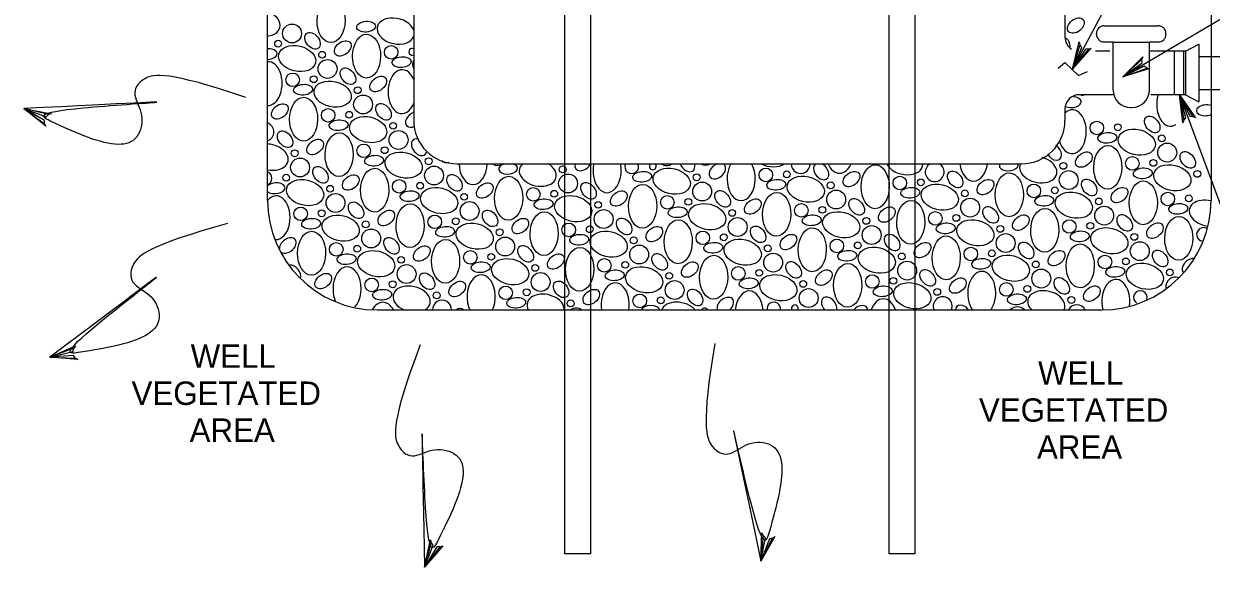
# Model space of a CAD drawing. Extents: x 636462 to 637367, y 299944 to 300538.
# Drawn here: x 636731.3 to 636883.5, y 300235.2 to 300304.9 of the extents above; entities that cross this region are included whole.
import ezdxf

# ---------------------------------------------------------------- set-up
doc = ezdxf.new("R2010")
doc.units = 0
doc.layers.add('1', color=7, linetype='Continuous')
doc.layers.add('Default', color=7, linetype='Continuous')

msp = doc.modelspace()

# ---------------------------------------------------------------- linework, layer by layer
at = {"layer": '1'}
msp.add_lwpolyline([(636863.84, 300299.17), (636864.72, 300299.91), (636866.46, 300298.24), (636867.63, 300298.74)], dxfattribs=at)
at = {"layer": 'Default'}
for p, q in [((636865.7, 300299.03), (636894.03, 300352.14)), ((636952.82, 300345.46), (636872.15, 300298.08)), ((636781.25, 300337), (636781.25, 300292.48)), ((636864.72, 300337), (636864.72, 300303.18)), ((636869.74, 300304.6), (636876.7, 300304.6)), ((636868.77, 300303.5), (636868.77, 300303.63)), ((636877.67, 300303.5), (636877.67, 300303.63)), ((636870.48, 300301.33), (636868.65, 300301.33)), ((636870.89, 300302.52), (636869.74, 300302.52)), ((636870.89, 300296.37), (636870.89, 300302.52)), ((636870.89, 300302.52), (636875.55, 300302.52)), ((636875.55, 300296.37), (636875.55, 300302.52)), ((636876.7, 300302.52), (636875.55, 300302.52)), ((636880.19, 300301.33), (636875.58, 300301.33)), ((636878.72, 300301.33), (636878.72, 300295.76)), ((636879.91, 300301.33), (636879.91, 300295.76)), ((636880.19, 300301.33), (636881.89, 300302.24)), ((636880.19, 300301.33), (636880.19, 300295.76)), ((636881.89, 300302.24), (636881.89, 300294.85)), ((636881.89, 300300.65), (636917.52, 300300.65)), ((636870.9, 300295.76), (636866.58, 300295.76)), ((636880.19, 300295.76), (636875.72, 300295.76)), ((636879.41, 300295.76), (636894.23, 300255.85)), ((636880.19, 300295.76), (636881.89, 300294.85)), ((636881.89, 300296.45), (636917.52, 300296.45)), ((636864.72, 300293.91), (636864.72, 300292.48)), ((636873.14, 300294.12), (636873.3, 300294.12)), ((636786.81, 300286.91), (636859.16, 300286.91)), ((636800.61, 300286.91), (636803.89, 300286.91)), ((636842.21, 300286.91), (636845.49, 300286.91))]:
    msp.add_line(p, q, dxfattribs=at)
for points in [[(636762.51, 300282.23), (636762.51, 300347.25)], [(636883.46, 300347.25), (636883.46, 300282.23)], [(636800.61, 300286.91), (636800.61, 300342.56)], [(636803.89, 300342.56), (636803.89, 300286.91)], [(636842.21, 300286.91), (636842.21, 300342.56)], [(636845.49, 300342.56), (636845.49, 300286.91)], [(636867.77, 300301.59), (636868.1, 300301.72), (636865.7, 300299.03), (636867.77, 300301.59), (636867.35, 300301.59), (636865.7, 300299.03), (636866.89, 300301.83), (636866.64, 300302.17), (636865.7, 300299.03), (636866.55, 300302.53), (636866.64, 300302.17)], [(636875.26, 300299.19), (636875.6, 300299.14), (636872.15, 300298.08), (636875.26, 300299.19), (636874.9, 300299.41), (636872.15, 300298.08), (636874.62, 300299.86), (636874.59, 300300.28), (636872.15, 300298.08), (636874.7, 300300.64), (636874.59, 300300.28)], [(636879.95, 300292.51), (636879.83, 300292.18), (636879.41, 300295.76), (636879.95, 300292.51), (636880.23, 300292.82), (636879.41, 300295.76), (636880.72, 300293.01), (636881.13, 300292.97), (636879.41, 300295.76), (636881.47, 300292.8), (636881.13, 300292.97)], [(636733.92, 300292.05), (636734.07, 300291.73), (636731.25, 300293.98), (636733.92, 300292.05), (636733.9, 300292.47), (636731.25, 300293.98), (636734.11, 300292.94), (636734.43, 300293.21), (636731.25, 300293.98), (636734.8, 300293.32), (636734.43, 300293.21)], [(636803.89, 300286.91), (636803.89, 300236.94), (636800.61, 300236.94), (636800.61, 300286.91)], [(636845.49, 300286.91), (636845.49, 300236.94), (636842.21, 300236.94), (636842.21, 300286.91)], [(636869.41, 300268.17), (636776.56, 300268.17)], [(636737.88, 300262.01), (636738.18, 300261.84), (636734.59, 300262.12), (636737.88, 300262.01), (636737.63, 300262.35), (636734.59, 300262.12), (636737.54, 300262.87), (636737.66, 300263.27), (636734.59, 300262.12), (636737.89, 300263.56), (636737.66, 300263.27)], [(636784.64, 300237.81), (636784.96, 300237.95), (636782.63, 300235.2), (636784.64, 300237.81), (636784.22, 300237.8), (636782.63, 300235.2), (636783.75, 300238.03), (636783.5, 300238.36), (636782.63, 300235.2), (636783.4, 300238.72), (636783.5, 300238.36)], [(636827.25, 300238.92), (636827.54, 300239.12), (636825.76, 300235.98), (636827.25, 300238.92), (636826.84, 300238.83), (636825.76, 300235.98), (636826.33, 300238.97), (636826.02, 300239.25), (636825.76, 300235.98), (636825.85, 300239.59), (636826.02, 300239.25)]]:
    msp.add_lwpolyline(points, dxfattribs=at)
for centre, radius in [((636765.64, 300303.62), 1.21), ((636763.86, 300302.31), 0.435), ((636769.5, 300300.89), 0.435), ((636778.35, 300301.21), 0.869), ((636770.2, 300299.07), 1.21), ((636765.73, 300297.68), 0.869), ((636768.42, 300297.75), 0.435), ((636774.05, 300296.34), 0.435), ((636774.75, 300294.52), 1.21), ((636770.28, 300293.13), 0.869), ((636772.97, 300293.2), 0.435), ((636778.6, 300291.78), 0.435), ((636868.82, 300291.51), 0.869), ((636871.51, 300291.59), 0.435), ((636779.3, 300289.97), 1.21), ((636877.14, 300290.17), 0.435), ((636774.83, 300288.58), 0.869), ((636777.52, 300288.65), 0.435), ((636877.84, 300288.35), 1.21), ((636766.67, 300286.44), 1.21), ((636765.98, 300288.26), 0.435), ((636783.16, 300287.23), 0.435), ((636873.37, 300286.96), 0.869), ((636876.06, 300287.03), 0.435), ((636783.85, 300285.41), 1.21), ((636800.34, 300286.2), 0.435), ((636826.38, 300285.49), 0.869), ((636829.07, 300285.56), 0.435), ((636865.21, 300284.83), 1.21), ((636864.52, 300286.64), 0.435), ((636881.7, 300285.62), 0.435), ((636764.89, 300285.13), 0.435), ((636779.38, 300284.02), 0.869), ((636782.07, 300284.1), 0.435), ((636801.03, 300284.39), 1.21), ((636818.22, 300283.36), 1.21), ((636817.52, 300285.18), 0.435), ((636834.7, 300284.15), 0.435), ((636843.56, 300284.46), 0.869), ((636846.25, 300284.54), 0.435), ((636860.74, 300283.44), 0.869), ((636771.22, 300281.89), 1.21), ((636770.53, 300283.71), 0.435), ((636787.71, 300282.68), 0.435), ((636796.57, 300283), 0.869), ((636799.26, 300283.07), 0.435), ((636813.75, 300281.97), 0.869), ((636835.4, 300282.33), 1.21), ((636851.89, 300283.12), 0.435), ((636863.43, 300283.51), 0.435), ((636877.92, 300282.41), 0.869), ((636880.61, 300282.48), 0.435), ((636766.75, 300280.5), 0.869), ((636788.41, 300280.86), 1.21), ((636804.89, 300281.65), 0.435), ((636816.44, 300282.04), 0.435), ((636830.93, 300280.94), 0.869), ((636833.62, 300281.01), 0.435), ((636852.58, 300281.3), 1.21), ((636869.76, 300280.27), 1.21), ((636869.07, 300282.09), 0.435), ((636769.44, 300280.57), 0.435), ((636783.94, 300279.47), 0.869), ((636786.63, 300279.54), 0.435), ((636805.59, 300279.83), 1.21), ((636822.77, 300278.81), 1.21), ((636822.07, 300280.62), 0.435), ((636839.26, 300279.59), 0.435), ((636848.11, 300279.91), 0.869), ((636850.8, 300279.98), 0.435), ((636865.29, 300278.88), 0.869), ((636775.78, 300277.34), 1.21), ((636775.08, 300279.15), 0.435), ((636792.26, 300278.13), 0.435), ((636801.12, 300278.44), 0.869), ((636803.81, 300278.52), 0.435), ((636818.3, 300277.42), 0.869), ((636839.95, 300277.78), 1.21), ((636856.44, 300278.57), 0.435), ((636867.98, 300278.96), 0.435), ((636771.31, 300275.95), 0.869), ((636792.96, 300276.31), 1.21), ((636809.44, 300277.1), 0.435), ((636820.99, 300277.49), 0.435), ((636835.48, 300276.39), 0.869), ((636838.17, 300276.46), 0.435), ((636857.13, 300276.75), 1.21), ((636874.32, 300275.72), 1.21), ((636873.62, 300277.54), 0.435), ((636774, 300276.02), 0.435), ((636788.49, 300274.92), 0.869), ((636791.18, 300274.99), 0.435), ((636810.14, 300275.28), 1.21), ((636827.32, 300274.25), 1.21), ((636826.63, 300276.07), 0.435), ((636843.81, 300275.04), 0.435), ((636852.66, 300275.36), 0.869), ((636855.36, 300275.43), 0.435), ((636869.85, 300274.33), 0.869), ((636780.33, 300272.78), 1.21), ((636779.63, 300274.6), 0.435), ((636796.82, 300273.57), 0.435), ((636805.67, 300273.89), 0.869), ((636808.36, 300273.96), 0.435), ((636822.85, 300272.86), 0.869), ((636844.5, 300273.22), 1.21), ((636860.99, 300274.01), 0.435), ((636872.54, 300274.4), 0.435), ((636775.86, 300271.39), 0.869), ((636797.51, 300271.76), 1.21), ((636814, 300272.55), 0.435), ((636825.54, 300272.94), 0.435), ((636840.03, 300271.83), 0.869), ((636842.73, 300271.91), 0.435), ((636861.69, 300272.2), 1.21), ((636878.17, 300272.99), 0.435), ((636778.55, 300271.47), 0.435), ((636793.04, 300270.37), 0.869), ((636795.73, 300270.44), 0.435), ((636814.69, 300270.73), 1.21), ((636831.87, 300269.7), 1.21), ((636831.18, 300271.52), 0.435), ((636848.36, 300270.49), 0.435), ((636857.22, 300270.81), 0.869), ((636859.91, 300270.88), 0.435), ((636784.19, 300270.05), 0.435), ((636801.37, 300269.02), 0.435), ((636810.22, 300269.34), 0.869), ((636812.91, 300269.41), 0.435), ((636865.54, 300269.46), 0.435)]:
    msp.add_circle(centre, radius, dxfattribs=at)
for centre, radius, start, end in [((636869.74, 300303.63), 0.974, 90, 180), ((636876.7, 300303.63), 0.974, 360, 90), ((636866.58, 300303.18), 1.86, 180, 237.7912), ((636864.18, 300302.01), 1.21, 352.7201, 61.4233), ((636869.74, 300303.5), 0.974, 180, 270), ((636876.7, 300303.5), 0.974, 270, 0), ((636781.05, 300301.28), 0.435, 62.7415, 297.2585), ((636866.58, 300293.91), 1.86, 90, 180), ((636866.96, 300296.14), 0.435, 240.305, 299.695), ((636873.14, 300296.37), 2.25, 180, 270), ((636873.3, 300296.37), 2.25, 270, 0), ((636762.12, 300290.99), 1.21, 288.7446, 71.2554), ((636786.81, 300292.48), 5.57, 180, 270), ((636859.16, 300292.48), 5.57, 270, 360), ((636762.2, 300285.05), 0.869, 290.6346, 69.3654), ((636792.01, 300287.55), 0.869, 227.2713, 312.7287), ((636809.19, 300286.52), 0.869, 153.3644, 26.6356), ((636811.89, 300286.59), 0.435, 133.1772, 46.8228), ((636813.66, 300287.91), 1.21, 235.6642, 304.3358), ((636830.85, 300286.88), 1.21, 178.6807, 1.3193), ((636848.03, 300285.85), 1.21, 119.3321, 60.6679), ((636776.56, 300282.23), 14.05, 180, 270), ((636869.41, 300282.23), 14.05, 270, 0), ((636882.48, 300277.86), 0.869, 58.5112, 260.9176), ((636878.87, 300271.17), 1.21, 68.7134, 188.0124), ((636874.4, 300269.78), 0.869, 344.543, 239.3176), ((636784.88, 300268.23), 1.21, 357.1734, 182.8266), ((636827.4, 300268.31), 0.869, 350.8755, 189.1245), ((636849.06, 300268.67), 1.21, 335.6413, 204.3587), ((636802.06, 300267.2), 1.21, 53.0783, 126.9217), ((636818.55, 300267.99), 0.435, 24.3232, 155.6768), ((636830.1, 300268.38), 0.435, 331.017, 208.983), ((636866.24, 300267.64), 1.21, 25.8695, 154.1305)]:
    msp.add_arc(centre, radius, start, end, dxfattribs=at)
for centre, major_axis, ratio in [((636770.65, 300305.26), (0.03, 2.81), 0.641702), ((636866.13, 300304.63), (0.938, 0.766), 0.672414), ((636775.14, 300304.49), (1.21, 0.09), 0.56568), ((636768.27, 300302.68), (-0.766, 0.938), 0.672414), ((636772.14, 300301.7), (0.938, 0.766), 0.672414), ((636775.2, 300300.71), (0.03, 2.81), 0.641702), ((636766.3, 300300.4), (-2.36, 0.55), 0.672414), ((636779.69, 300299.94), (1.21, 0.09), 0.56568), ((636772.82, 300298.13), (-0.766, 0.938), 0.672414), ((636776.7, 300297.14), (0.938, 0.766), 0.672414), ((636767.06, 300296.41), (1.21, 0.09), 0.56568), ((636770.85, 300295.84), (-2.36, 0.55), 0.672414), ((636767.12, 300292.63), (0.03, 2.81), 0.641702), ((636764.07, 300293.62), (0.938, 0.766), 0.672414), ((636777.38, 300293.58), (-0.766, 0.938), 0.672414), ((636771.62, 300291.86), (1.21, 0.09), 0.56568), ((636775.4, 300291.29), (-2.36, 0.55), 0.672414), ((636875.92, 300291.96), (-0.766, 0.938), 0.672414), ((636764.75, 300290.06), (-0.766, 0.938), 0.672414), ((636771.68, 300288.08), (0.03, 2.81), 0.641702), ((636870.16, 300290.24), (1.21, 0.09), 0.56568), ((636873.94, 300289.68), (-2.36, 0.55), 0.672414), ((636768.62, 300289.07), (0.938, 0.766), 0.672414), ((636870.22, 300286.46), (0.03, 2.81), 0.641702), ((636776.17, 300287.31), (1.21, 0.09), 0.56568), ((636779.95, 300286.74), (-2.36, 0.55), 0.672414), ((636867.16, 300287.45), (0.938, 0.766), 0.672414), ((636880.47, 300287.41), (-0.766, 0.938), 0.672414), ((636769.3, 300285.5), (-0.766, 0.938), 0.672414), ((636776.23, 300283.53), (0.03, 2.81), 0.641702), ((636810.53, 300285.25), (1.21, 0.09), 0.56568), ((636814.32, 300284.68), (-2.36, 0.55), 0.672414), ((636837.35, 300284.95), (0.938, 0.766), 0.672414), ((636840.4, 300283.97), (0.03, 2.81), 0.641702), ((636850.66, 300284.91), (-0.766, 0.938), 0.672414), ((636874.71, 300285.69), (1.21, 0.09), 0.56568), ((636878.49, 300285.12), (-2.36, 0.55), 0.672414), ((636767.32, 300283.22), (-2.36, 0.55), 0.672414), ((636773.17, 300284.51), (0.938, 0.766), 0.672414), ((636786.48, 300284.47), (-0.766, 0.938), 0.672414), ((636790.36, 300283.48), (0.938, 0.766), 0.672414), ((636793.41, 300282.5), (0.03, 2.81), 0.641702), ((636803.66, 300283.45), (-0.766, 0.938), 0.672414), ((636810.59, 300281.47), (0.03, 2.81), 0.641702), ((636827.72, 300284.22), (1.21, 0.09), 0.56568), ((636831.5, 300283.66), (-2.36, 0.55), 0.672414), ((636848.68, 300282.63), (-2.36, 0.55), 0.672414), ((636854.53, 300283.92), (0.938, 0.766), 0.672414), ((636857.59, 300282.94), (0.03, 2.81), 0.641702), ((636867.84, 300283.89), (-0.766, 0.938), 0.672414), ((636874.77, 300281.91), (0.03, 2.81), 0.641702), ((636780.72, 300282.76), (1.21, 0.09), 0.56568), ((636784.51, 300282.19), (-2.36, 0.55), 0.672414), ((636801.69, 300281.16), (-2.36, 0.55), 0.672414), ((636807.54, 300282.46), (0.938, 0.766), 0.672414), ((636820.85, 300282.42), (-0.766, 0.938), 0.672414), ((636827.77, 300280.44), (0.03, 2.81), 0.641702), ((636844.9, 300283.2), (1.21, 0.09), 0.56568), ((636862.08, 300282.17), (1.21, 0.09), 0.56568), ((636865.86, 300281.6), (-2.36, 0.55), 0.672414), ((636871.71, 300282.9), (0.938, 0.766), 0.672414), ((636773.85, 300280.95), (-0.766, 0.938), 0.672414), ((636780.78, 300278.98), (0.03, 2.81), 0.641702), ((636797.9, 300281.73), (1.21, 0.09), 0.56568), ((636815.09, 300280.7), (1.21, 0.09), 0.56568), ((636818.87, 300280.13), (-2.36, 0.55), 0.672414), ((636824.72, 300281.43), (0.938, 0.766), 0.672414), ((636838.03, 300281.39), (-0.766, 0.938), 0.672414), ((636841.9, 300280.4), (0.938, 0.766), 0.672414), ((636844.96, 300279.41), (0.03, 2.81), 0.641702), ((636855.21, 300280.36), (-0.766, 0.938), 0.672414), ((636879.26, 300281.14), (1.21, 0.09), 0.56568), ((636768.09, 300279.23), (1.21, 0.09), 0.56568), ((636771.88, 300278.66), (-2.36, 0.55), 0.672414), ((636777.73, 300279.96), (0.938, 0.766), 0.672414), ((636791.03, 300279.92), (-0.766, 0.938), 0.672414), ((636794.91, 300278.93), (0.938, 0.766), 0.672414), ((636797.96, 300277.95), (0.03, 2.81), 0.641702), ((636808.22, 300278.89), (-0.766, 0.938), 0.672414), ((636815.15, 300276.92), (0.03, 2.81), 0.641702), ((636832.27, 300279.67), (1.21, 0.09), 0.56568), ((636836.05, 300279.1), (-2.36, 0.55), 0.672414), ((636853.24, 300278.07), (-2.36, 0.55), 0.672414), ((636859.08, 300279.37), (0.938, 0.766), 0.672414), ((636862.14, 300278.39), (0.03, 2.81), 0.641702), ((636872.39, 300279.33), (-0.766, 0.938), 0.672414), ((636879.32, 300277.36), (0.03, 2.81), 0.641702), ((636768.15, 300275.45), (0.03, 2.81), 0.641702), ((636785.27, 300278.2), (1.21, 0.09), 0.56568), ((636789.06, 300277.63), (-2.36, 0.55), 0.672414), ((636806.24, 300276.61), (-2.36, 0.55), 0.672414), ((636812.09, 300277.9), (0.938, 0.766), 0.672414), ((636825.4, 300277.87), (-0.766, 0.938), 0.672414), ((636832.33, 300275.89), (0.03, 2.81), 0.641702), ((636849.45, 300278.64), (1.21, 0.09), 0.56568), ((636866.63, 300277.61), (1.21, 0.09), 0.56568), ((636870.42, 300277.05), (-2.36, 0.55), 0.672414), ((636876.27, 300278.34), (0.938, 0.766), 0.672414), ((636778.4, 300276.4), (-0.766, 0.938), 0.672414), ((636785.33, 300274.42), (0.03, 2.81), 0.641702), ((636802.46, 300277.18), (1.21, 0.09), 0.56568), ((636819.64, 300276.15), (1.21, 0.09), 0.56568), ((636823.42, 300275.58), (-2.36, 0.55), 0.672414), ((636829.27, 300276.88), (0.938, 0.766), 0.672414), ((636842.58, 300276.84), (-0.766, 0.938), 0.672414), ((636846.45, 300275.85), (0.938, 0.766), 0.672414), ((636849.51, 300274.86), (0.03, 2.81), 0.641702), ((636859.76, 300275.81), (-0.766, 0.938), 0.672414), ((636772.64, 300274.68), (1.21, 0.09), 0.56568), ((636776.43, 300274.11), (-2.36, 0.55), 0.672414), ((636782.28, 300275.41), (0.938, 0.766), 0.672414), ((636795.59, 300275.37), (-0.766, 0.938), 0.672414), ((636799.46, 300274.38), (0.938, 0.766), 0.672414), ((636802.52, 300273.39), (0.03, 2.81), 0.641702), ((636812.77, 300274.34), (-0.766, 0.938), 0.672414), ((636819.7, 300272.37), (0.03, 2.81), 0.641702), ((636836.82, 300275.12), (1.21, 0.09), 0.56568), ((636840.61, 300274.55), (-2.36, 0.55), 0.672414), ((636857.79, 300273.52), (-2.36, 0.55), 0.672414), ((636863.64, 300274.82), (0.938, 0.766), 0.672414), ((636866.69, 300273.83), (0.03, 2.81), 0.641702), ((636876.94, 300274.78), (-0.766, 0.938), 0.672414), ((636789.83, 300273.65), (1.21, 0.09), 0.56568), ((636793.61, 300273.08), (-2.36, 0.55), 0.672414), ((636810.79, 300272.05), (-2.36, 0.55), 0.672414), ((636816.64, 300273.35), (0.938, 0.766), 0.672414), ((636829.95, 300273.31), (-0.766, 0.938), 0.672414), ((636836.88, 300271.34), (0.03, 2.81), 0.641702), ((636854, 300274.09), (1.21, 0.09), 0.56568), ((636871.18, 300273.06), (1.21, 0.09), 0.56568), ((636874.97, 300272.49), (-2.36, 0.55), 0.672414), ((636769.65, 300271.88), (0.938, 0.766), 0.672414), ((636782.96, 300271.85), (-0.766, 0.938), 0.672414), ((636807.01, 300272.62), (1.21, 0.09), 0.56568), ((636824.19, 300271.59), (1.21, 0.09), 0.56568), ((636827.98, 300271.03), (-2.36, 0.55), 0.672414), ((636833.82, 300272.32), (0.938, 0.766), 0.672414), ((636847.13, 300272.29), (-0.766, 0.938), 0.672414), ((636851.01, 300271.3), (0.938, 0.766), 0.672414), ((636864.32, 300271.26), (-0.766, 0.938), 0.672414), ((636777.2, 300270.13), (1.21, 0.09), 0.56568), ((636786.83, 300270.86), (0.938, 0.766), 0.672414), ((636800.14, 300270.82), (-0.766, 0.938), 0.672414), ((636804.01, 300269.83), (0.938, 0.766), 0.672414), ((636817.32, 300269.79), (-0.766, 0.938), 0.672414), ((636841.37, 300270.57), (1.21, 0.09), 0.56568), ((636845.16, 300270), (-2.36, 0.55), 0.672414), ((636868.19, 300270.27), (0.938, 0.766), 0.672414), ((636794.38, 300269.1), (1.21, 0.09), 0.56568), ((636858.56, 300269.54), (1.21, 0.09), 0.56568)]:
    msp.add_ellipse(centre, major_axis=major_axis, ratio=ratio, dxfattribs=at)
for centre, major_axis, ratio, start_param, end_param in [((636761.74, 300304.95), (-2.36, 0.55), 0.672414, 2.052765, 4.543621), ((636778.93, 300303.92), (-2.36, 0.55), 0.672414, 3.538888, 9.340684), ((636762.51, 300300.97), (1.21, 0.09), 0.56568, 4.667524, 7.816111), ((636762.57, 300297.19), (0.03, 2.81), 0.641702, 3.122831, 6.334752), ((636783.48, 300299.37), (-2.36, 0.55), 0.672414, 6.078453, 6.801119), ((636779.75, 300296.16), (0.03, 2.81), 0.641702, 5.322796, 10.417972), ((636865.6, 300294.8), (1.21, 0.09), 0.56568, 3.917971, 7.627832), ((636878.29, 300294.54), (0.03, 2.81), 0.641702, 1.127817, 3.535515), ((636781.25, 300292.59), (0.938, 0.766), 0.672414, 1.073393, 4.331942), ((636865.66, 300291.02), (0.03, 2.81), 0.641702, 1.987509, 6.849708), ((636882.79, 300293.77), (1.21, 0.09), 0.56568, 0.94046, 5.25999), ((636762.77, 300287.77), (-2.36, 0.55), 0.672414, 1.616232, 4.980155), ((636781.93, 300289.03), (-0.766, 0.938), 0.672414, 5.417078, 10.025288), ((636863.29, 300288.44), (-0.766, 0.938), 0.672414, 1.353215, 5.110128), ((636785.8, 300288.04), (0.938, 0.766), 0.672414, 3.071586, 4.213186), ((636861.31, 300286.15), (-2.36, 0.55), 0.672414, 6.150666, 10.942532), ((636788.86, 300287.05), (0.03, 2.81), 0.641702, 1.628185, 4.668509), ((636793.35, 300286.28), (1.21, 0.09), 0.56568, 1.865215, 7.302292), ((636797.14, 300285.71), (-2.36, 0.55), 0.672414, 5.824819, 10.555091), ((636802.98, 300287.01), (0.938, 0.766), 0.672414, 2.360012, 5.301208), ((636806.04, 300286.02), (0.03, 2.81), 0.641702, 1.256252, 5.040443), ((636816.29, 300286.97), (-0.766, 0.938), 0.672414, 1.125703, 4.153449), ((636818.67, 300289.55), (0.03, 2.81), 0.641702, 2.800771, 3.495924), ((636820.17, 300285.98), (0.938, 0.766), 0.672414, 1.048859, 6.612361), ((636823.22, 300285), (0.03, 2.81), 0.641702, 0.826768, 5.469927), ((636826.95, 300288.21), (-2.36, 0.55), 0.672414, 1.218856, 2.594684), ((636833.48, 300285.94), (-0.766, 0.938), 0.672414, 6.223878, 11.621645), ((636835.85, 300288.52), (0.03, 2.81), 0.641702, 2.188676, 4.108019), ((636844.13, 300287.18), (-2.36, 0.55), 0.672414, 0.497186, 3.316354), ((636853.03, 300287.49), (0.03, 2.81), 0.641702, 1.786444, 4.510251), ((636857.53, 300286.72), (1.21, 0.09), 0.56568, 2.734355, 6.433152), ((636763.54, 300283.78), (1.21, 0.09), 0.56568, 3.651621, 8.832014), ((636763.6, 300280), (0.03, 2.81), 0.641702, 3.135673, 6.95019), ((636883.05, 300280.57), (-2.36, 0.55), 0.672414, 4.695967, 7.984833), ((636765.1, 300276.44), (0.938, 0.766), 0.672414, 3.195325, 8.958243), ((636765.78, 300272.87), (-0.766, 0.938), 0.672414, 3.577182, 5.844038), ((636772.7, 300270.9), (0.03, 2.81), 0.641702, 3.742318, 8.442004), ((636880.82, 300273.79), (0.938, 0.766), 0.672414, 0.595259, 3.15593), ((636789.89, 300269.87), (0.03, 2.81), 0.641702, 4.069357, 8.510523), ((636854.06, 300270.31), (0.03, 2.81), 0.641702, 3.853086, 8.726794), ((636871.24, 300269.28), (0.03, 2.81), 0.641702, 4.489695, 8.25871), ((636780.98, 300269.56), (-2.36, 0.55), 0.672414, 2.507832, 7.588893), ((636807.07, 300268.84), (0.03, 2.81), 0.641702, 4.478215, 8.101665), ((636824.25, 300267.81), (0.03, 2.81), 0.641702, 4.847302, 7.732578), ((636862.34, 300268.97), (-2.36, 0.55), 0.672414, 2.983127, 7.113598), ((636777.26, 300266.35), (0.03, 2.81), 0.641702, 5.428023, 7.139713), ((636798.16, 300268.53), (-2.36, 0.55), 0.672414, 3.263251, 6.833474), ((636815.35, 300267.5), (-2.36, 0.55), 0.672414, 3.888405, 6.20832), ((636821.19, 300268.8), (0.938, 0.766), 0.672414, 4.717851, 9.226554), ((636834.5, 300268.76), (-0.766, 0.938), 0.672414, 3.628389, 7.933948), ((636841.43, 300266.79), (0.03, 2.81), 0.641702, 5.23608, 7.343799), ((636787.51, 300267.29), (-0.766, 0.938), 0.672414, 5.174822, 6.387515), ((636811.56, 300268.07), (1.21, 0.09), 0.56568, 0.020065, 2.864256), ((636838.38, 300267.77), (0.938, 0.766), 0.672414, 5.817761, 8.126644), ((636851.69, 300267.73), (-0.766, 0.938), 0.672414, 4.63371, 6.928628), ((636858.61, 300265.76), (0.03, 2.81), 0.641702, 5.755653, 6.824227)]:
    msp.add_ellipse(centre, major_axis=major_axis, ratio=ratio, start_param=start_param, end_param=end_param, dxfattribs=at)
for points in [[(636759.71, 300295.42), (636749.72, 300298.82), (636746.12, 300298.05), (636745.04, 300295.71), (636746.76, 300293.29), (636746.04, 300289.98), (636743.59, 300289.08), (636739.61, 300290.11), (636734.59, 300292.43), (636731.25, 300293.98), (636759.71, 300295.42), (636731.25, 300293.98)], [(636757.37, 300279.24), (636747.19, 300276.47), (636744.63, 300273.82), (636745.04, 300271.27), (636747.82, 300270.23), (636749.08, 300267.08), (636747.56, 300264.97), (636743.68, 300263.59), (636738.22, 300262.71), (636734.59, 300262.12), (636757.37, 300279.24), (636734.59, 300262.12)], [(636782.06, 300263.69), (636778.35, 300253.81), (636779.01, 300250.18), (636781.32, 300249.03), (636783.78, 300250.68), (636787.08, 300249.86), (636787.9, 300247.39), (636786.75, 300243.43), (636784.28, 300238.49), (636782.63, 300235.2), (636782.06, 300263.69), (636782.63, 300235.2)], [(636819.86, 300263.86), (636818.07, 300253.46), (636819.4, 300250.02), (636821.88, 300249.32), (636823.99, 300251.4), (636827.38, 300251.21), (636828.65, 300248.94), (636828.26, 300244.84), (636826.76, 300239.53), (636825.76, 300235.98), (636819.86, 300263.86), (636825.76, 300235.98)]]:
    msp.add_open_spline(points, degree=3, dxfattribs=at)

# ---------------------------------------------------------------- texts
for s, p in [('WELL', (636752.65, 300260.76)), ('WELL', (636861.28, 300258.6)), ('VEGETATED', (636745.07, 300256.01)), ('VEGETATED', (636853.7, 300253.85)), ('AREA', (636752.52, 300251.27)), ('AREA', (636861.15, 300249.11))]:
    msp.add_text(s, height=2.998, dxfattribs=at).set_placement(p)

doc.saveas('drawing.dxf')
